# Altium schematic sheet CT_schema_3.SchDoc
size 298 x 247 mm
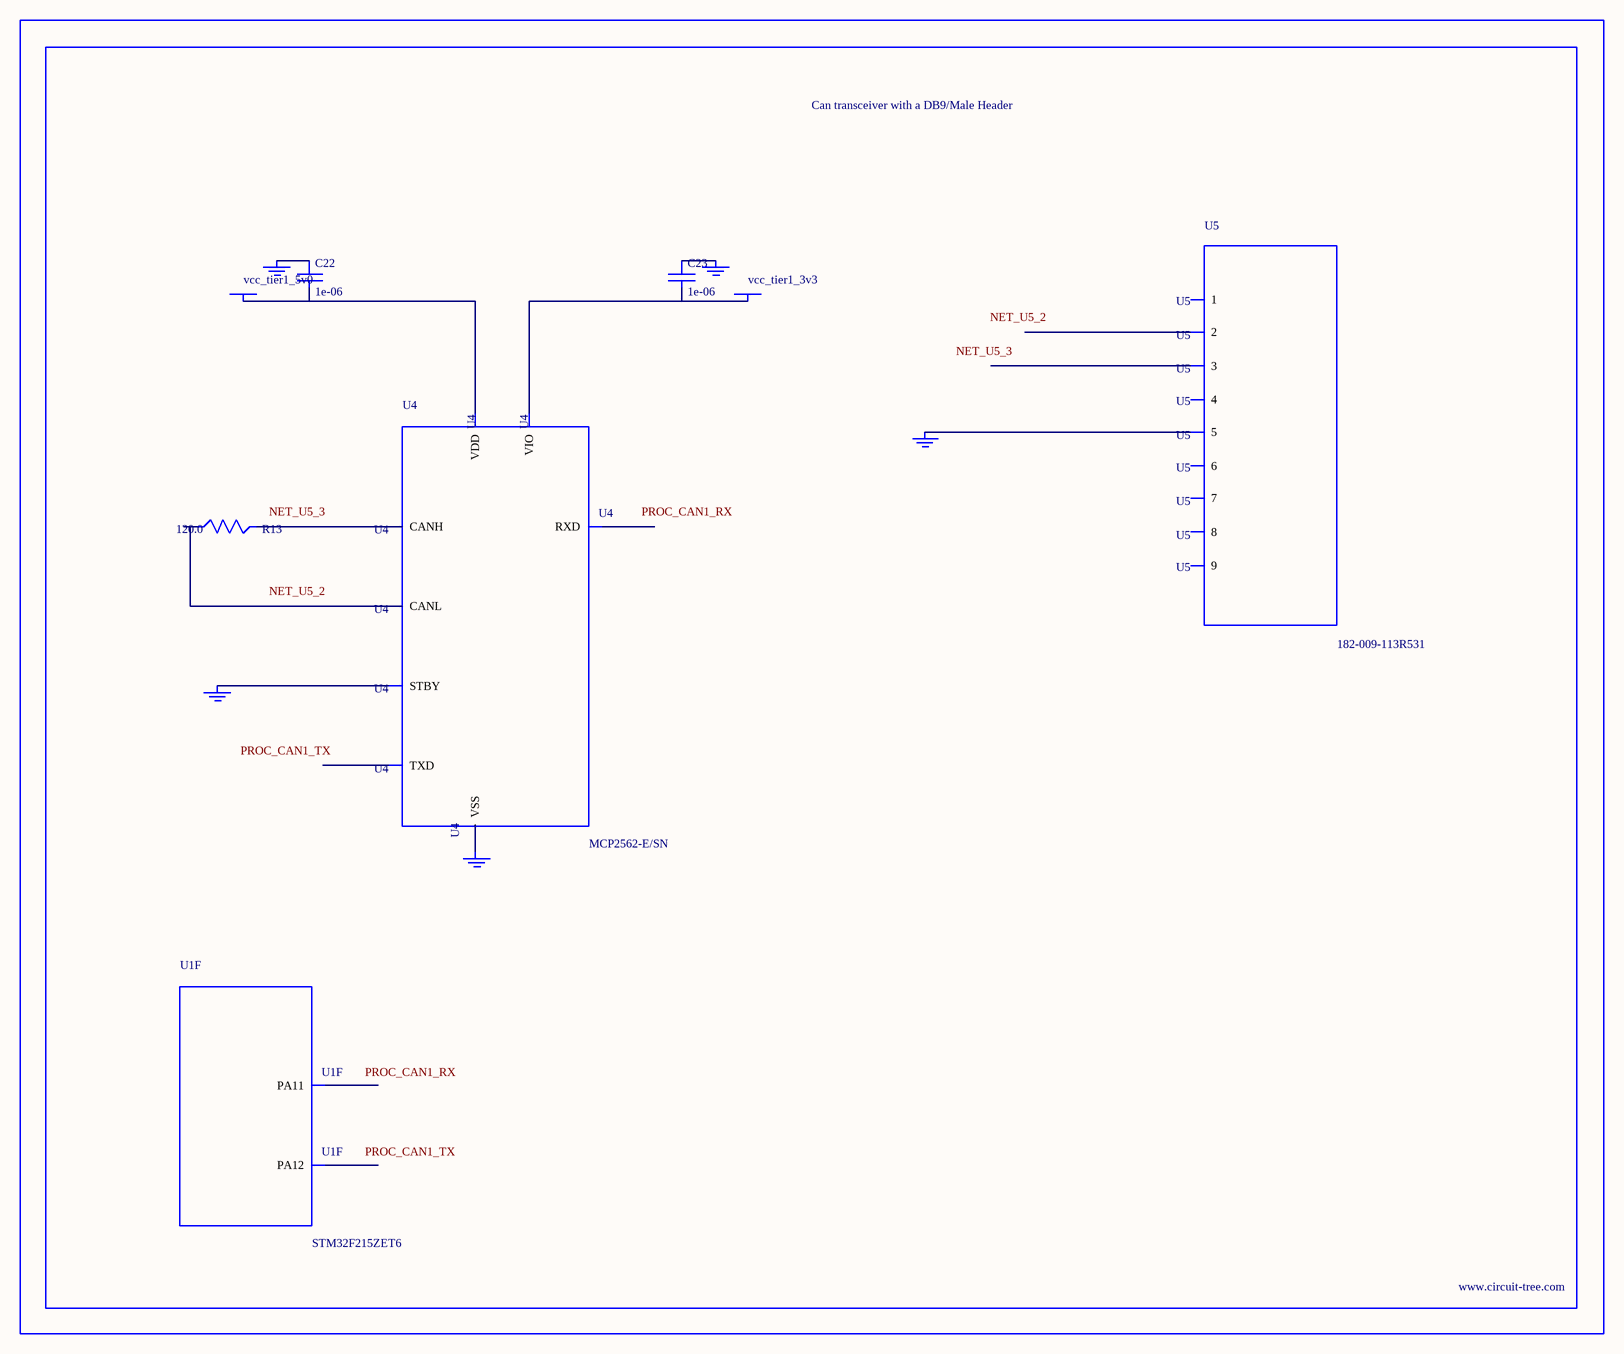
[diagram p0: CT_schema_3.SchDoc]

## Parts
BORDER2  (no value)
C22  1e-06  [C0603]
C23  1e-06  [C0603]
GND_INSTANCE_2_0  (no value)
GND_INSTANCE_2_1  (no value)
GND_INSTANCE_2_2  (no value)
GND_INSTANCE_2_3  (no value)
GND_INSTANCE_2_4  (no value)
POWER_INSTANCE_2_0  vcc_tier1_5v0
POWER_INSTANCE_2_1  vcc_tier1_3v3
R13  120.0  [R0603]
U1  STM32F215ZET6  [LQFP144]  (part F of 12)
U4  MCP2562-E/SN  [SOIC-8]
U5  182-009-113R531  [182-009-MALE]

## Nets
NetC22_1: C22.1 GND_INSTANCE_2_0.0(GND)
NetC22_2: C22.2 POWER_INSTANCE_2_0.0(PWR) U4.3(VDD)
NetC23_1: C23.1 GND_INSTANCE_2_1.0(GND)
NetC23_2: C23.2 POWER_INSTANCE_2_1.0(PWR) U4.5(VIO)
NetGND_INSTANCE_2_2_0: GND_INSTANCE_2_2.0(GND) U4.8(STBY)
NetGND_INSTANCE_2_3_0: GND_INSTANCE_2_3.0(GND) U4.2(VSS)
NetGND_INSTANCE_2_4_0: GND_INSTANCE_2_4.0(GND) U5.5
NetR13_1: R13.1 U4.6(CANL)
NetR13_2: R13.2 U4.7(CANH)

Not connected (* = marked no-connect by the designer): U1 103(PA11) 104(PA12); U4 1(TXD) 4(RXD); U5 1 2 3 4 6 7 8 9

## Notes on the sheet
- Labels drawn without touching a wire or pin: NET_U5_2, NET_U5_3, PROC_CAN1_RX, PROC_CAN1_TX

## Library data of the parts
BORDER2 = BORDER_PAGE2
C22 C23 = C0603C105K3RACTU
GND_INSTANCE_2_0-GND_INSTANCE_2_4 = GND
POWER_INSTANCE_2_0 POWER_INSTANCE_2_1 = PWR
R13 = RC0603JR-07120RL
